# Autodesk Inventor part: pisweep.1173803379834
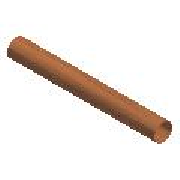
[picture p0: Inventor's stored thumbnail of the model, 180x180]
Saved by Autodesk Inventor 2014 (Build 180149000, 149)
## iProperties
NAME: PIPING: ASTM B 88 Tube
DATA: <meta><inlinegroups number="1" deflen="254"></inlinegroups><connections number="2"></connections><angles><a>3.14159265358979</a></angles></meta>
Company: Autodesk, Inc.
Created: 2007-02
Material: Copper
Description: Pipe
Document SubType Name: Modeling
Standard: ASTM B 88
Designer: Autodesk, Inc.
Standard Revision: 2003
Standards Organization: ANSI
Language: en-US
Size Designation: 2 - Type L - 100
Categories: <MemberInstance><Categories><Category DisplayName="Tube &amp; Pipe" InternalName="4347fa0f-2144-441d-94cd-e3e15c92b736" Mnemonic="TUBEANDPIPE"><CategoryParamete
Stock Number: ASTM B 88 Tube 2 - Type L
Density: 8.94 g/cm^3
Mass: 1828.05 g
Surface Area: 2305.95 cm^2
Volume: 204.48 cm^3
Appearance: Copper
L: 27.612 in
PL: 27.612 in
Author: Autodesk, Inc.
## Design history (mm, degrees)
sketch "3D Sketch1" dims "d4" = 50.7999, "d5" = 50.7999
workpoint "Work Point3"
workpoint "Work Point4"
workpoint "Work Point5"
workpoint "Work Point6"
workplane "Work Plane1"
sketch "Sketch3"
  geometry: C1 r 26.988 at (0, 0); C2 r 25.209 at (0, 0); 1 further point
  constraints: 2 centre point
workpoint "Work Point7"
sweep "Sweep1" dims "d6" = 0
body "Solid1"
other parameters: "OD" = 53.975 [user parameter], "t" = 1.778 [user parameter], "L" = 701.3448 (= PL) [user parameter], "ID" = 50.419 [user parameter], "PL" = 701.3448 [user parameter; used in 1 equation term], "Size_Designation" = 12.345 [user parameter]
